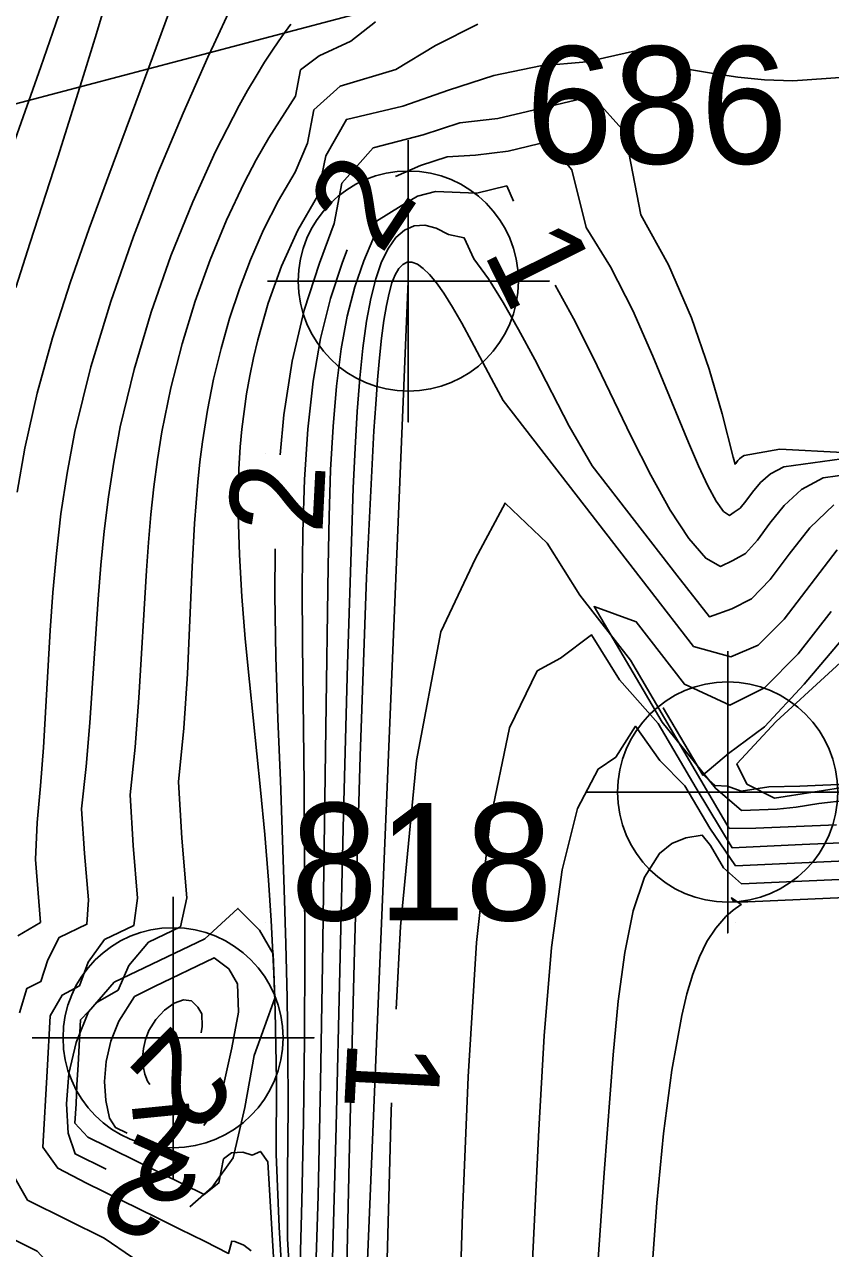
# Model space of a CAD drawing. Extents: x 2602990 to 2605851, y 618069 to 619180.
# Drawn here: x 2603644.86 to 2603662.03, y 618453.06 to 618479.12 of the extents above; entities that cross this region are included whole.
import ezdxf

# ---------------------------------------------------------------- set-up
doc = ezdxf.new("R2010")
doc.units = 0
for name, color, linetype in [('DTM Contours Major', 7, 'Continuous'), ('DTM Contours Major Text', 7, 'Continuous'), ('DTM Contours Minor', 7, 'Continuous'), ('DTM Contours Minor Text', 7, 'Continuous'), ('Exist DTM Breakline', 7, 'Continuous'), ('Exist DTM Breakline Cogo Number', 7, 'Continuous'), ('Exist DTM Breakline Cogo Point CELL', 7, 'Continuous'), ('Exist DTM Crownline', 7, 'Continuous'), ('Exist DTM QL2 LIDAR Elevation Point', 7, 'Continuous'), ('Exist DTM Regular Point CELL', 7, 'Continuous'), ('Exist DTM Regular Point Cogo Number', 7, 'Continuous'), ('Exist DTM Regular Point Underwater CELL', 7, 'Continuous'), ('Exist Roads EOP', 7, 'Continuous'), ('PH Exist DTM Obscure Area', 7, 'Continuous')]:
    doc.layers.add(name, color=color, linetype=linetype)

# ---------------------------------------------------------------- blocks, each defined once
blk = doc.blocks.new('EXIST DTM BREAKLINE COGO POINT')
at = {"layer": 'Exist DTM Breakline Cogo Point CELL'}
blk.add_lwpolyline([(0, 0.06), (0, -0.06), (0, 0), (0.06, 0), (-0.06, 0)], dxfattribs=at)
blk.add_circle((0, 0), 0.04688, dxfattribs=at)
blk = doc.blocks.new('EXIST DTM REGULAR POINT UNDERWATER')
at = {"layer": 'Exist DTM Regular Point Underwater CELL'}
blk.add_lwpolyline([(0, 0.06), (0, -0.06), (0, 0), (0.06, 0), (-0.06, 0)], dxfattribs=at)
blk.add_circle((0, 0), 0.04688, dxfattribs=at)
blk = doc.blocks.new('EXIST DTM REGULAR POINT')
at = {"layer": 'Exist DTM Regular Point CELL'}
blk.add_lwpolyline([(0, 0.06), (0, -0.06), (0, 0), (0.06, 0), (-0.06, 0)], dxfattribs=at)
blk.add_circle((0, 0), 0.04688, dxfattribs=at)

msp = doc.modelspace()

# ---------------------------------------------------------------- linework, layer by layer
at = {"layer": 'DTM Contours Major'}
for points in [[(2603662.337, 618478.002), (2603661.221, 618477.921), (2603660.622, 618477.942), (2603660.05, 618478.003), (2603659.491, 618478.087), (2603658.936, 618478.178), (2603658.662, 618478.421), (2603658.253, 618478.646), (2603656.84, 618478.331), (2603655.85, 618478.24), (2603654.857, 618478.039), (2603653.893, 618477.723), (2603652.918, 618477.384), (2603651.718, 618477.101), (2603651.284, 618476.328), (2603651.101, 618475.467), (2603650.681, 618474.742), (2603650.335, 618473.978), (2603650.055, 618473.193), (2603649.833, 618472.409), (2603649.742, 618472.023), (2603649.663, 618471.642), (2603649.595, 618471.263), (2603649.539, 618470.885), (2603649.494, 618470.508), (2603649.459, 618470.129), (2603649.431, 618469.659), (2603649.417, 618469.182), (2603649.416, 618468.696), (2603649.44, 618467.835), (2603649.493, 618466.947), (2603649.566, 618466.041), (2603649.653, 618465.127), (2603649.89, 618462.83), (2603649.98, 618461.876), (2603650.059, 618460.906), (2603650.117, 618460.049), (2603650.175, 618458.924), (2603650.203, 618458.124), (2603650.231, 618456.642), (2603650.221, 618455.071), (2603650.289, 618453.519), (2603650.508, 618449.758)], [(2603649.87, 618459.838), (2603649.41, 618460.305), (2603648.707, 618459.659), (2603646.776, 618458.736), (2603646.231, 618458.099), (2603645.965, 618457.447), (2603645.809, 618456.789), (2603645.756, 618456.142), (2603645.796, 618455.522), (2603645.943, 618455.076), (2603646.604, 618454.75)], [(2603648.382, 618453.953), (2603648.86, 618454.368), (2603649.305, 618454.997), (2603649.555, 618456.069), (2603649.758, 618457.171), (2603650.195, 618458.393), (2603650.161, 618459.336), (2603649.87, 618459.838)]]:
    msp.add_lwpolyline(points, dxfattribs=at)
at = {"layer": 'DTM Contours Minor'}
for points in [[(2603647.581, 618486.76), (2603647.574, 618486.718), (2603647.343, 618485.564), (2603647.06, 618484.338), (2603646.732, 618483.063), (2603646.366, 618481.763), (2603645.967, 618480.462), (2603645.595, 618479.331), (2603645.212, 618478.219), (2603644.07, 618475.007)], [(2603646.67, 618479.843), (2603646.397, 618478.929), (2603646.123, 618478.037), (2603645.573, 618476.301), (2603644.983, 618474.483), (2603644.678, 618473.523)], [(2603648.142, 618479.942), (2603647.514, 618478.211), (2603646.657, 618475.913), (2603646.241, 618474.78), (2603645.838, 618473.623), (2603645.464, 618472.451), (2603645.136, 618471.276), (2603644.871, 618470.106), (2603644.709, 618469.165)], [(2603649.258, 618479.476), (2603648.893, 618478.698), (2603648.768, 618478.426), (2603648.24, 618477.237), (2603647.705, 618475.956), (2603647.184, 618474.611), (2603646.702, 618473.228), (2603646.279, 618471.834), (2603645.94, 618470.458), (2603645.771, 618469.573), (2603645.641, 618468.707), (2603645.543, 618467.86), (2603645.469, 618467.031), (2603645.412, 618466.22), (2603645.266, 618463.727), (2603645.208, 618462.915), (2603645.135, 618462.131), (2603645.098, 618461.349), (2603645.208, 618460.005), (2603644.725, 618459.723)], [(2603650.535, 618479.127), (2603650.347, 618478.868), (2603650.161, 618478.599), (2603649.978, 618478.319), (2603649.797, 618478.026), (2603649.616, 618477.719), (2603649.436, 618477.398), (2603648.935, 618476.423), (2603648.446, 618475.349), (2603647.983, 618474.201), (2603647.562, 618473.002), (2603647.198, 618471.778), (2603646.905, 618470.554), (2603646.764, 618469.807), (2603646.652, 618469.067), (2603646.562, 618468.336), (2603646.491, 618467.61), (2603646.433, 618466.89), (2603646.254, 618464.254), (2603646.178, 618463.324), (2603646.081, 618462.423), (2603646.144, 618461.471), (2603646.226, 618460.488), (2603646.192, 618459.967), (2603645.602, 618459.684), (2603645.359, 618459.211), (2603645.216, 618458.746), (2603644.915, 618458.6), (2603644.76, 618458.079)], [(2603652.336, 618479.182), (2603651.812, 618478.771), (2603651.14, 618478.453), (2603650.744, 618478.155), (2603650.634, 618477.595), (2603650.067, 618476.712), (2603649.797, 618476.245), (2603649.539, 618475.754), (2603649.165, 618474.959), (2603648.817, 618474.116), (2603648.501, 618473.234), (2603648.221, 618472.323), (2603647.983, 618471.391), (2603647.79, 618470.448), (2603647.696, 618469.864), (2603647.618, 618469.278), (2603647.555, 618468.689), (2603647.503, 618468.096), (2603647.459, 618467.499), (2603647.297, 618464.786), (2603647.218, 618463.74), (2603647.112, 618462.721), (2603647.175, 618461.644), (2603647.268, 618460.519), (2603647.195, 618459.943), (2603646.57, 618459.643), (2603646.218, 618459.163), (2603646.033, 618458.656), (2603645.667, 618458.458), (2603645.408, 618458.018), (2603645.347, 618456.839), (2603645.257, 618455.219), (2603645.572, 618454.771), (2603646.184, 618454.457), (2603647.673, 618453.725), (2603648.171, 618453.475), (2603648.699, 618453.217), (2603649.209, 618452.958), (2603649.281, 618453.22), (2603649.342, 618453.216), (2603649.535, 618453.131), (2603649.691, 618453.015)], [(2603654.515, 618479.131), (2603653.619, 618478.679), (2603652.77, 618478.168), (2603651.583, 618477.811), (2603651.027, 618477.307), (2603650.89, 618476.6), (2603650.625, 618475.98), (2603650.27, 618475.378), (2603649.956, 618474.754), (2603649.678, 618474.113), (2603649.442, 618473.494), (2603649.232, 618472.865), (2603649.049, 618472.225), (2603648.892, 618471.574), (2603648.76, 618470.911), (2603648.654, 618470.235), (2603648.601, 618469.81), (2603648.556, 618469.379), (2603648.519, 618468.942), (2603648.487, 618468.496), (2603648.436, 618467.576), (2603648.332, 618465.301), (2603648.257, 618464.14), (2603648.146, 618463), (2603648.213, 618461.798), (2603648.321, 618460.528), (2603648.185, 618459.914), (2603647.507, 618459.587), (2603647.085, 618459.091), (2603646.857, 618458.566), (2603646.425, 618458.316), (2603646.058, 618457.931), (2603646.008, 618456.974), (2603645.981, 618456.55), (2603645.962, 618456.141), (2603645.937, 618455.731), (2603646.212, 618455.433), (2603646.629, 618455.231), (2603647.338, 618454.878), (2603648.691, 618454.21), (2603649.005, 618454.461), (2603649.099, 618454.972), (2603649.273, 618455.098), (2603649.513, 618455.115), (2603649.715, 618455.052), (2603649.887, 618455.129), (2603650.048, 618454.907), (2603650.334, 618450.015)], [(2603660.191, 618469.946), (2603660.947, 618470.081), (2603662.285, 618470.014), (2603664.032, 618469.852), (2603666.14, 618469.74), (2603668.132, 618469.731), (2603670.005, 618469.894), (2603670.368, 618469.974), (2603670.72, 618470.068), (2603671.063, 618470.175), (2603671.397, 618470.293), (2603671.477, 618470.365), (2603677.23, 618475.863), (2603678.731, 618477.289), (2603680.484, 618478.16), (2603682.716, 618476.332), (2603684.2, 618475.724), (2603685.617, 618474.711), (2603686.9, 618473.382), (2603687.984, 618471.826), (2603688.804, 618470.132), (2603689.239, 618468.703)], [(2603650.305, 618469.958), (2603650.387, 618470.811), (2603650.566, 618471.954), (2603650.817, 618473.04), (2603651.145, 618474.044), (2603651.455, 618474.885), (2603651.618, 618475.743), (2603652.291, 618476.494), (2603653.355, 618476.773), (2603654.132, 618477.028), (2603654.945, 618477.123), (2603656.959, 618477.598), (2603657.649, 618476.831), (2603657.991, 618475.074), (2603658.58, 618474.01), (2603659.063, 618472.88), (2603659.441, 618471.787), (2603659.72, 618470.837), (2603659.956, 618469.91), (2603659.994, 618469.761), (2603659.995, 618469.766), (2603660.012, 618469.78), (2603660.054, 618469.839), (2603660.086, 618469.877), (2603660.13, 618469.914), (2603660.191, 618469.946)], [(2603652.767, 618475.887), (2603653.298, 618476.121), (2603653.867, 618476.308), (2603654.466, 618476.344), (2603655.164, 618476.43), (2603656.018, 618476.633), (2603656.517, 618476.031), (2603656.822, 618474.803), (2603657.343, 618473.966), (2603657.816, 618473.035), (2603658.246, 618472.063), (2603658.999, 618470.227), (2603659.214, 618469.729), (2603659.414, 618469.304), (2603659.594, 618468.973), (2603659.75, 618468.754), (2603659.877, 618468.67), (2603659.972, 618468.739), (2603660.1, 618468.825), (2603660.226, 618468.977), (2603660.365, 618469.167), (2603660.534, 618469.371), (2603660.749, 618469.56), (2603661.029, 618469.709)], [(2603651.048, 618451.992), (2603651.115, 618454.188), (2603651.169, 618456.592), (2603651.213, 618459.113), (2603651.281, 618464.14), (2603651.327, 618467.59), (2603651.349, 618468.648), (2603651.383, 618469.64), (2603651.434, 618470.565), (2603651.508, 618471.426), (2603651.61, 618472.221), (2603651.737, 618472.911), (2603651.896, 618473.538), (2603652.089, 618474.093), (2603652.283, 618474.546), (2603652.361, 618474.935), (2603652.885, 618475.263), (2603653.235, 618475.468), (2603653.617, 618475.566), (2603654.494, 618475.534), (2603655.131, 618475.687), (2603655.279, 618475.362)], [(2603651.416, 618452.59), (2603651.498, 618455.661), (2603651.659, 618462.306), (2603651.743, 618465.495), (2603651.831, 618468.336), (2603651.866, 618469.256), (2603651.904, 618470.104), (2603651.949, 618470.882), (2603652.002, 618471.591), (2603652.068, 618472.232), (2603652.148, 618472.806), (2603652.238, 618473.287), (2603652.345, 618473.708), (2603652.469, 618474.067), (2603652.612, 618474.361), (2603652.773, 618474.588), (2603652.955, 618474.748), (2603653.162, 618474.837), (2603653.389, 618474.852), (2603653.632, 618474.79), (2603653.889, 618474.65), (2603654.226, 618474.578), (2603654.432, 618474.132), (2603654.741, 618473.712), (2603655.058, 618473.207), (2603655.386, 618472.628), (2603655.728, 618471.988), (2603656.462, 618470.574), (2603656.951, 618469.726), (2603658.757, 618467.398), (2603659.453, 618466.511), (2603659.926, 618466.685), (2603660.343, 618466.892), (2603660.739, 618467.309), (2603661.143, 618467.844), (2603661.586, 618468.405), (2603662.096, 618468.9)], [(2603650.732, 618452.742), (2603650.772, 618454.07), (2603650.804, 618455.766), (2603650.823, 618457.527), (2603650.83, 618459.328), (2603650.827, 618461.14), (2603650.816, 618462.937), (2603650.786, 618465.94), (2603650.78, 618467.148), (2603650.79, 618468.313), (2603650.826, 618469.434), (2603650.897, 618470.506), (2603651.012, 618471.528), (2603651.169, 618472.44), (2603651.377, 618473.291), (2603651.638, 618474.065), (2603651.732, 618474.325)], [(2603651.7, 618451.399), (2603651.784, 618455.247), (2603651.888, 618459.406), (2603652.009, 618463.549), (2603652.149, 618467.347), (2603652.306, 618470.472), (2603652.343, 618471.039), (2603652.382, 618471.557), (2603652.423, 618472.026), (2603652.468, 618472.447), (2603652.517, 618472.819), (2603652.571, 618473.143), (2603652.627, 618473.404), (2603652.689, 618473.622), (2603652.757, 618473.797), (2603652.833, 618473.929), (2603652.917, 618474.017), (2603653.01, 618474.062), (2603653.114, 618474.064), (2603653.229, 618474.02), (2603653.353, 618473.932), (2603653.488, 618473.799), (2603653.634, 618473.621), (2603653.791, 618473.4), (2603653.975, 618473.108), (2603654.173, 618472.766), (2603654.385, 618472.38), (2603654.857, 618471.487), (2603655.057, 618471.117), (2603658.168, 618467.104), (2603659.111, 618465.884), (2603659.903, 618465.658), (2603660.486, 618465.907), (2603661.036, 618466.461), (2603662.165, 618467.94)], [(2603656.163, 618473.577), (2603656.556, 618472.864), (2603656.965, 618472.05), (2603657.784, 618470.352), (2603658.201, 618469.529), (2603658.613, 618468.786), (2603659.006, 618468.177), (2603659.369, 618467.759), (2603659.687, 618467.585), (2603659.949, 618467.712), (2603660.214, 618467.863), (2603660.468, 618468.145), (2603660.734, 618468.503), (2603661.04, 618468.881), (2603661.409, 618469.223), (2603661.867, 618469.473)], [(2603660.244, 618462.953), (2603660.034, 618463.384), (2603660.872, 618464.287), (2603663.096, 618466.326), (2603664.515, 618467.378), (2603666.057, 618468.289), (2603666.847, 618468.459), (2603669.535, 618468.445), (2603670.23, 618468.476), (2603675.423, 618469.646), (2603676.483, 618470.391), (2603677.271, 618471.078), (2603678.011, 618471.29), (2603678.73, 618471.477), (2603679.301, 618471.782), (2603679.848, 618472.306), (2603680.501, 618472.604), (2603681.22, 618471.908), (2603681.911, 618471.272), (2603682.419, 618470.942), (2603682.86, 618470.543), (2603683.092, 618470.25)], [(2603661.029, 618469.709), (2603662.264, 618469.877)], [(2603661.867, 618469.473), (2603663.09, 618469.64)], [(2603662.153, 618462.087), (2603660.433, 618462.01), (2603659.871, 618462.009), (2603657.766, 618465.591), (2603656.691, 618466.975), (2603655.994, 618468.08), (2603655.098, 618468.934), (2603654.469, 618467.752), (2603653.727, 618466.192), (2603653.208, 618463.451), (2603652.871, 618459.92), (2603652.781, 618458.16)], [(2603650.726, 618448.77), (2603650.464, 618453.267), (2603650.467, 618454.639), (2603650.477, 618456.099), (2603650.471, 618457.252), (2603650.454, 618458.402), (2603650.429, 618459.553), (2603650.396, 618460.706), (2603650.313, 618463.029), (2603650.261, 618464.343), (2603650.217, 618465.662), (2603650.195, 618466.976), (2603650.204, 618467.961)], [(2603662.398, 618462.61), (2603661.776, 618462.535), (2603661.298, 618462.457), (2603660.888, 618462.42), (2603660.13, 618462.386), (2603659.574, 618462.863), (2603658.439, 618464.27), (2603656.993, 618466.731), (2603657.891, 618466.403), (2603658.916, 618465.077), (2603659.879, 618464.631), (2603660.622, 618465.001), (2603661.334, 618465.721), (2603662.04, 618466.625)], [(2603662.916, 618461.73), (2603661.423, 618461.666), (2603659.93, 618461.597), (2603659.163, 618462.862), (2603658.355, 618464.238), (2603657.53, 618465.17), (2603656.934, 618466.132), (2603656.28, 618465.634), (2603655.78, 618465.361), (2603655.193, 618464.146), (2603654.775, 618462.135), (2603654.491, 618459.577), (2603654.308, 618456.72), (2603654.191, 618453.814), (2603654.074, 618450.1)], [(2603662.524, 618462.96), (2603661.373, 618462.905), (2603660.711, 618462.894), (2603660.126, 618462.803), (2603659.834, 618462.909), (2603659.572, 618462.922), (2603659.29, 618463.171), (2603658.465, 618464.574), (2603659.31, 618463.138), (2603659.856, 618463.604), (2603660.618, 618464.169), (2603661.467, 618465.078), (2603662.376, 618466.151)], [(2603664.547, 618461.414), (2603660.004, 618461.21), (2603659.456, 618462.014), (2603658.927, 618462.914), (2603658.389, 618463.453), (2603657.872, 618464.184), (2603657.452, 618463.525), (2603657.08, 618463.27), (2603656.638, 618462.432), (2603656.315, 618461.128), (2603656.088, 618459.474), (2603655.929, 618457.588), (2603655.815, 618455.587), (2603655.658, 618452.362)], [(2603662.463, 618462.909), (2603660.835, 618462.65), (2603660.244, 618462.953)], [(2603665.421, 618461.064), (2603660.13, 618460.828), (2603659.747, 618461.168), (2603659.469, 618461.642), (2603659.296, 618461.861), (2603658.949, 618461.81), (2603658.646, 618461.688), (2603658.385, 618461.476), (2603658.068, 618460.969), (2603657.827, 618460.255), (2603657.645, 618459.365), (2603657.508, 618458.331), (2603657.4, 618457.184), (2603657.21, 618454.674), (2603656.927, 618450.696)], [(2603666.327, 618460.717), (2603660.267, 618460.443), (2603659.968, 618460.442), (2603659.917, 618460.527), (2603660.125, 618460.39), (2603659.952, 618460.268), (2603659.794, 618460.129), (2603659.581, 618459.886), (2603659.396, 618459.601), (2603659.235, 618459.272), (2603659.094, 618458.901), (2603658.969, 618458.485), (2603658.858, 618458.026), (2603658.644, 618456.857), (2603658.47, 618455.513), (2603658.328, 618454.039), (2603658.212, 618452.477)], [(2603649.212, 618459.021), (2603648.904, 618459.251), (2603647.632, 618458.645), (2603647.204, 618458.426), (2603646.873, 618457.903), (2603646.702, 618457.477), (2603646.602, 618457.046), (2603646.568, 618456.621), (2603646.594, 618456.214), (2603646.675, 618455.838), (2603646.802, 618455.642), (2603647.048, 618455.52)], [(2603648.686, 618455.682), (2603648.849, 618455.916), (2603649.111, 618456.571), (2603649.28, 618457.335), (2603649.422, 618458.093), (2603649.4, 618458.697), (2603649.212, 618459.021)], [(2603648.555, 618458.204), (2603648.424, 618458.336), (2603648.248, 618458.356), (2603648.049, 618458.285), (2603647.847, 618458.14), (2603647.662, 618457.941), (2603647.515, 618457.707), (2603647.439, 618457.515), (2603647.395, 618457.321), (2603647.38, 618457.128), (2603647.391, 618456.945), (2603647.427, 618456.775), (2603647.485, 618456.626), (2603647.533, 618456.552)], [(2603648.628, 618457.652), (2603648.648, 618457.792), (2603648.638, 618458.059), (2603648.555, 618458.204)], [(2603652.679, 618456.163), (2603652.67, 618455.99), (2603652.563, 618452.052)], [(2603644.579, 618454.702), (2603644.932, 618454.094), (2603645.787, 618453.668), (2603646.564, 618453.287), (2603647.161, 618452.873)], [(2603644.182, 618453.475), (2603645.138, 618453.008), (2603645.666, 618452.432), (2603646.071, 618451.829), (2603646.422, 618451.255), (2603646.809, 618450.69), (2603648.001, 618450.096), (2603647.256, 618449.68), (2603646.497, 618449.192), (2603646.211, 618448.691), (2603645.883, 618448.212), (2603645.257, 618448.002), (2603644.622, 618447.558)]]:
    msp.add_lwpolyline(points, dxfattribs=at)
at = {"layer": 'Exist DTM Breakline'}
msp.add_line((2603651.819, 618444.348), (2603653.037, 618473.66), dxfattribs=at)
at = {"layer": 'Exist DTM Crownline'}
msp.add_spline([(2603233.488, 618380.754), (2603285.185, 618400.095), (2603335.457, 618418.629), (2603390.812, 618439.069), (2603440.087, 618457.325), (2603493.996, 618477.231), (2603542.655, 618495.301), (2603600.808, 618516.867), (2603653.659, 618536.362), (2603706.222, 618555.742), (2603764.811, 618577.593), (2603823.52, 618599.847), (2603878.564, 618620.56), (2603937.951, 618643.078), (2603997.369, 618665.789), (2604036.209, 618680.665), (2604055.311, 618688.017)], degree=3, dxfattribs=at)
at = {"layer": 'Exist DTM QL2 LIDAR Elevation Point'}
for p, q in [((2603650, 618470), (2603650, 618470)), ((2603660, 618470), (2603660, 618470)), ((2603650, 618460), (2603650, 618460)), ((2603660, 618460), (2603660, 618460))]:
    msp.add_line(p, q, dxfattribs=at)
at = {"layer": 'Exist Roads EOP'}
for points in [[(2603230.17, 618389.98), (2603282.929, 618409.597), (2603332.773, 618427.868), (2603388.167, 618448.413), (2603437.203, 618466.721), (2603490.778, 618486.527), (2603539.039, 618504.558), (2603597.451, 618526.156), (2603651.053, 618545.972), (2603705.208, 618566.084), (2603762.02, 618587.183), (2603820.334, 618609.162), (2603876.341, 618629.99), (2603934.909, 618652.28), (2603996.409, 618675.568), (2604033.216, 618689.957), (2604052.01, 618697.199)], [(2604034.633, 618668.486), (2603984.89, 618650.123), (2603936.767, 618631.654), (2603888.195, 618613.335), (2603837.766, 618594.258), (2603782.918, 618573.705), (2603731.939, 618554.39), (2603671.126, 618532.171), (2603621.822, 618514.106), (2603561.545, 618491.877), (2603506.421, 618471.293), (2603452.163, 618451.33), (2603398.364, 618431.316), (2603341.431, 618410.355), (2603281.65, 618388.199), (2603223.033, 618366.475), (2603185.717, 618352.612)]]:
    msp.add_spline(points, degree=3, dxfattribs=at)
at = {"layer": 'PH Exist DTM Obscure Area'}
msp.add_lwpolyline([(2603890.105, 618554.081), (2603884.134, 618554.138), (2603877.564, 618556.245), (2603871.962, 618557.136), (2603864.912, 618553.51), (2603864.071, 618543.545), (2603853.53, 618535.106), (2603836.557, 618528.64), (2603798.765, 618518.118), (2603619.02, 618470.66), (2603609.341, 618470.414), (2603597.75, 618470.282), (2603595.263, 618473.117), (2603594.69, 618475.565), (2603599.712, 618477.668), (2603611.669, 618481.486)], dxfattribs=at)

# ---------------------------------------------------------------- block references
at = {"layer": 'Exist DTM Breakline Cogo Point CELL', "xscale": 50, "yscale": 50}
msp.add_blockref('EXIST DTM BREAKLINE COGO POINT', (2603653.037, 618473.66), dxfattribs=at)
at = {"layer": 'Exist DTM Regular Point CELL', "xscale": 50, "yscale": 50}
msp.add_blockref('EXIST DTM REGULAR POINT', (2603648.029, 618457.55), dxfattribs=at)
at = {"layer": 'Exist DTM Regular Point Underwater CELL', "xscale": 50, "yscale": 50}
msp.add_blockref('EXIST DTM REGULAR POINT UNDERWATER', (2603659.838, 618462.782), dxfattribs=at)

# ---------------------------------------------------------------- texts
at = {"layer": 'DTM Contours Major Text'}
msp.add_text('2', height=2, rotation=155.8632, dxfattribs=at).set_placement((2603648.503, 618454.947))
at = {"layer": 'DTM Contours Minor Text'}
for s, rotation, p in [('2', 56.4673, (2603652.454, 618474.193)), ('1', 296.3274, (2603654.619, 618474.274)), ('2', 87.1076, (2603651.205, 618468.258)), ('2', 225.1535, (2603648.067, 618457.881)), ('1', 267.0778, (2603651.747, 618457.527)), ('2', 185.6542, (2603648.501, 618456.164))]:
    msp.add_text(s, height=2, rotation=rotation, dxfattribs=at).set_placement(p)
at = {"layer": 'Exist DTM Breakline Cogo Number'}
msp.add_text('686', height=2.5, dxfattribs=at).set_placement((2603655.537, 618476.16))
at = {"layer": 'Exist DTM Regular Point Cogo Number'}
msp.add_text('818', height=2.5, dxfattribs=at).set_placement((2603650.529, 618460.05))

doc.saveas('drawing.dxf')
